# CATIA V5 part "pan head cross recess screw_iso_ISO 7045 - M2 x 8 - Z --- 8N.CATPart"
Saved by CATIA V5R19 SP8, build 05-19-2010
Part number: pan head cross recess screw_iso_ISO 7045 - M2 x 8 - Z --- 8N
Revision: ANY
Definition: UNKNOWN
Nomenclature: pan head cross recess screw_iso_ISO 7045 - M2 x 8 - Z --- 8N
Source: Unknown
Bounding box of the stored display mesh (mm): x 0.032 to 9.6, y -2 to 2, z -2 to 2
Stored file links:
  D:\Documents\1_Travail\1 - ac-limoges.fr\ac-limoges.fr\Emmanuel Maynard - STI2D_Turgot\2 -2I2D\2_SEQUENCE_Serrure_Biométrique\5-Spé_ITEC\Serrure_Bio_Eleve\pan head cross recess screw_iso_ISO 7045 - M2 x 8 - Z --- 8N.CATPart
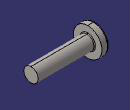
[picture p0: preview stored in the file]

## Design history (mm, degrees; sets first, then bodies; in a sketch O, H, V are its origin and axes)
Body1 "RecessCore" (main body)
  Solid1: solid without history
